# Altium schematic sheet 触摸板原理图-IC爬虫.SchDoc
size A4
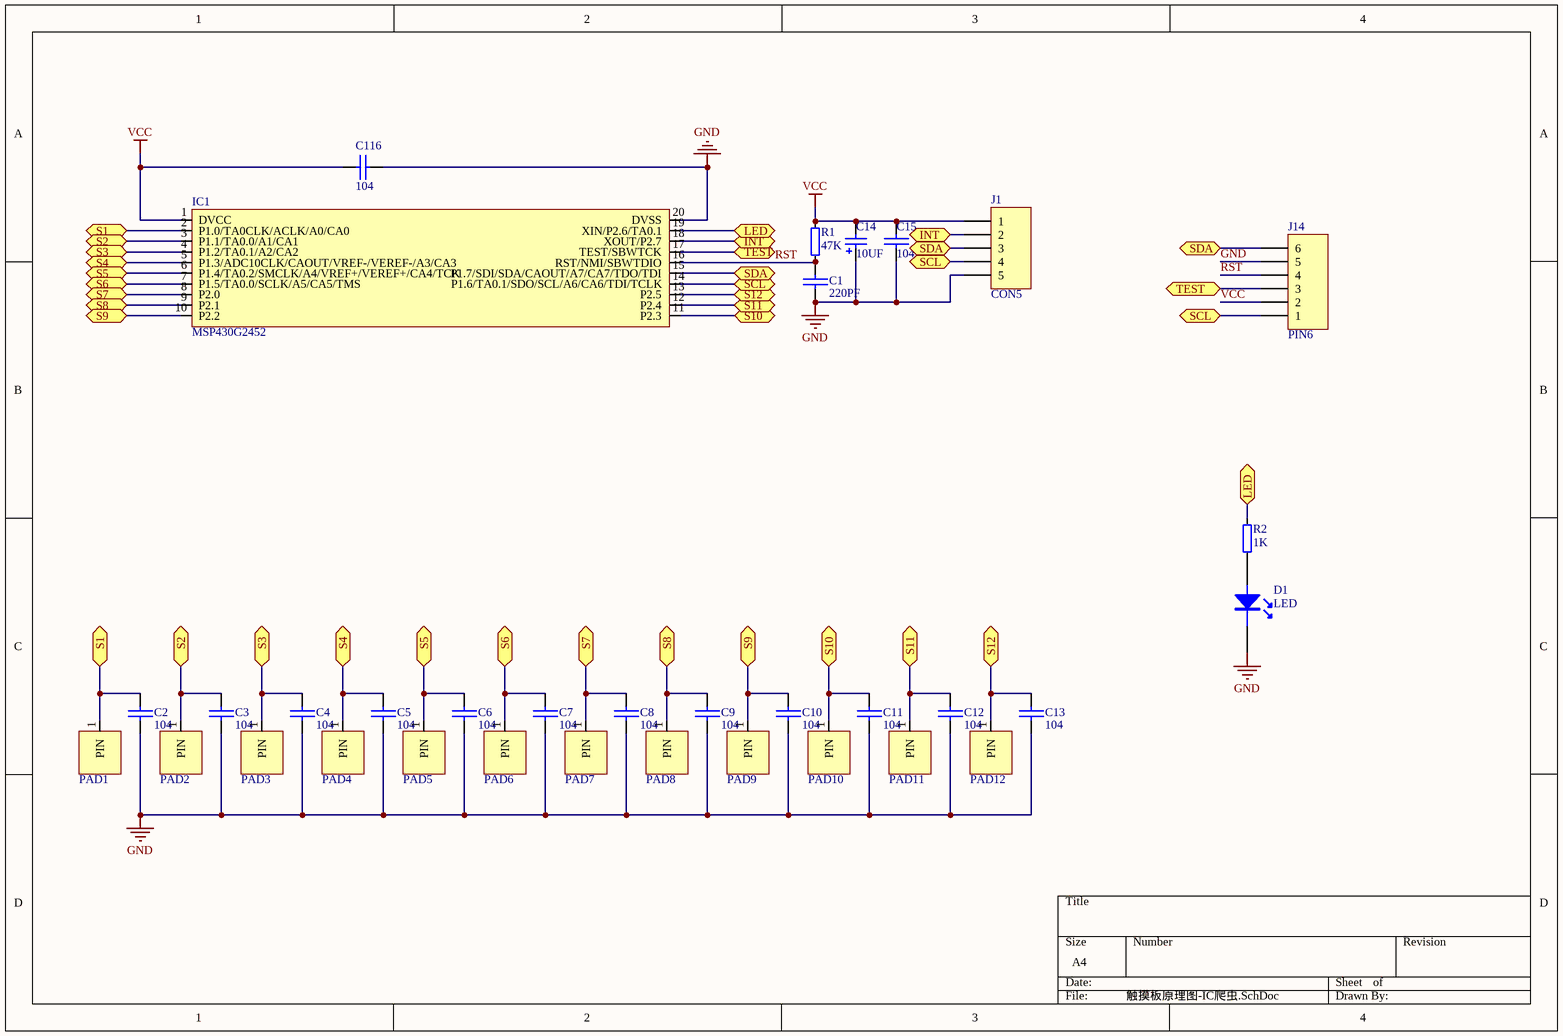
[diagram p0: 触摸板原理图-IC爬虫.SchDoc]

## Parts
C1  220PF  [RAD0.1]
C2  104  [C0805]
C3  104  [C0805]
C4  104  [RAD0.1]
C5  104  [RAD0.1]
C6  104  [RAD0.1]
C7  104  [RAD0.1]
C8  104  [RAD0.1]
C9  104  [RAD0.1]
C10  104  [RAD0.1]
C11  104  [RAD0.1]
C12  104  [RAD0.1]
C13  104  [RAD0.1]
C14  value 10UF  [POLAR0.8]  (hidden comment: Cap Pol2)
C15  104  [RAD0.1]
C116  104  [RAD0.1]
D1  LED  [1.6X0.8X0.6]
IC1  MSP430G2452  [PW020]
J1  CON5  [MHDR1X5]
J14  PIN6  [HDR1X6]
PAD1  TOUCHPAD  [TOUCHPAD]  (value not drawn)
PAD2  TOUCHPAD  (value not drawn)
PAD3  TOUCHPAD  (value not drawn)
PAD4  TOUCHPAD  (value not drawn)
PAD5  TOUCHPAD  (value not drawn)
PAD6  TOUCHPAD  (value not drawn)
PAD7  TOUCHPAD  (value not drawn)
PAD8  TOUCHPAD  (value not drawn)
PAD9  TOUCHPAD  (value not drawn)
PAD10  TOUCHPAD  (value not drawn)
PAD11  TOUCHPAD  (value not drawn)
PAD12  TOUCHPAD  (value not drawn)
R1  47K  [AXIAL0.3]
R2  1K  [AXIAL0.3]

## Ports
INT, LED, S1, S2, S3, S4, S5, S6, S7, S8, S9, S10, S11, S12, SCL, SDA, TEST

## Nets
GND: C1.2 C2.2 C3.2 C4.2 C5.2 C6.2 C7.2 C8.2 C9.2 C10.2 C11.2 C12.2 C13.2 C14.1 C15.2 C116.2 D1.K IC1.20(DVSS) J1.5 J14.5
VCC: C14.2 C15.1 C116.1 IC1.1(DVCC) J1.1 J14.2 R1.2
INT: IC1.18(XOUT/P2.7) J1.2 ; port INT
LED: IC1.19(XIN/P2.6/TA0.1) R2.2 ; port LED
RST: C1.1 IC1.16(RST/NMI/SBWTDIO) J14.4 R1.1
S1: C2.1 IC1.2(P1.0/TA0CLK/ACLK/A0/CA0) PAD1.1(PIN) ; port S1
S2: C3.1 IC1.3(P1.1/TA0.0/A1/CA1) PAD2.1(PIN) ; port S2
S3: C4.1 IC1.4(P1.2/TA0.1/A2/CA2) PAD3.1(PIN) ; port S3
S4: C5.1 IC1.5(P1.3/ADC10CLK/CAOUT/VREF-/VEREF-/A3/CA3) PAD4.1(PIN) ; port S4
S5: C6.1 IC1.6(P1.4/TA0.2/SMCLK/A4/VREF+/VEREF+/CA4/TCK) PAD5.1(PIN) ; port S5
S6: C7.1 IC1.7(P1.5/TA0.0/SCLK/A5/CA5/TMS) PAD6.1(PIN) ; port S6
S7: C8.1 IC1.8(P2.0) PAD7.1(PIN) ; port S7
S8: C9.1 IC1.9(P2.1) PAD8.1(PIN) ; port S8
S9: C10.1 IC1.10(P2.2) PAD9.1(PIN) ; port S9
S10: C11.1 IC1.11(P2.3) PAD10.1(PIN) ; port S10
S11: C12.1 IC1.12(P2.4) PAD11.1(PIN) ; port S11
S12: C13.1 IC1.13(P2.5) PAD12.1(PIN) ; port S12
SCL: IC1.14(P1.6/TA0.1/SDO/SCL/A6/CA6/TDI/TCLK) J1.4 J14.1 ; port SCL
SDA: IC1.15(P1.7/SDI/SDA/CAOUT/A7/CA7/TDO/TDI) J1.3 J14.6 ; port SDA
TEST: IC1.17(TEST/SBWTCK) J14.3 ; port TEST
NetD1_A: D1.A R2.1

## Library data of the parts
C1-C13 C15 C116 = 普通电容: Capacitor
C14 = Cap Pol2: Polarized Capacitor (Axial)
J1 = MHDR1X5: Header, 5-Pin
J14 = Header 6: Header, 6-Pin
R1 R2 = RES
